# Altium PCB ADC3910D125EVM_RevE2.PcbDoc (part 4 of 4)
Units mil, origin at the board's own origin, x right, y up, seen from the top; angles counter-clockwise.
Board outline 4000 x 2716.54 mil, 6 copper layers (Top Layer, L2 GND, L3 PWR, L4 PWR, L5 GND, Bottom Layer), stack 60.99 mil thick; 318 components, 203 nets, 1298 pads, 559 vias.
Unrouted connection lines stored in the file: 5.
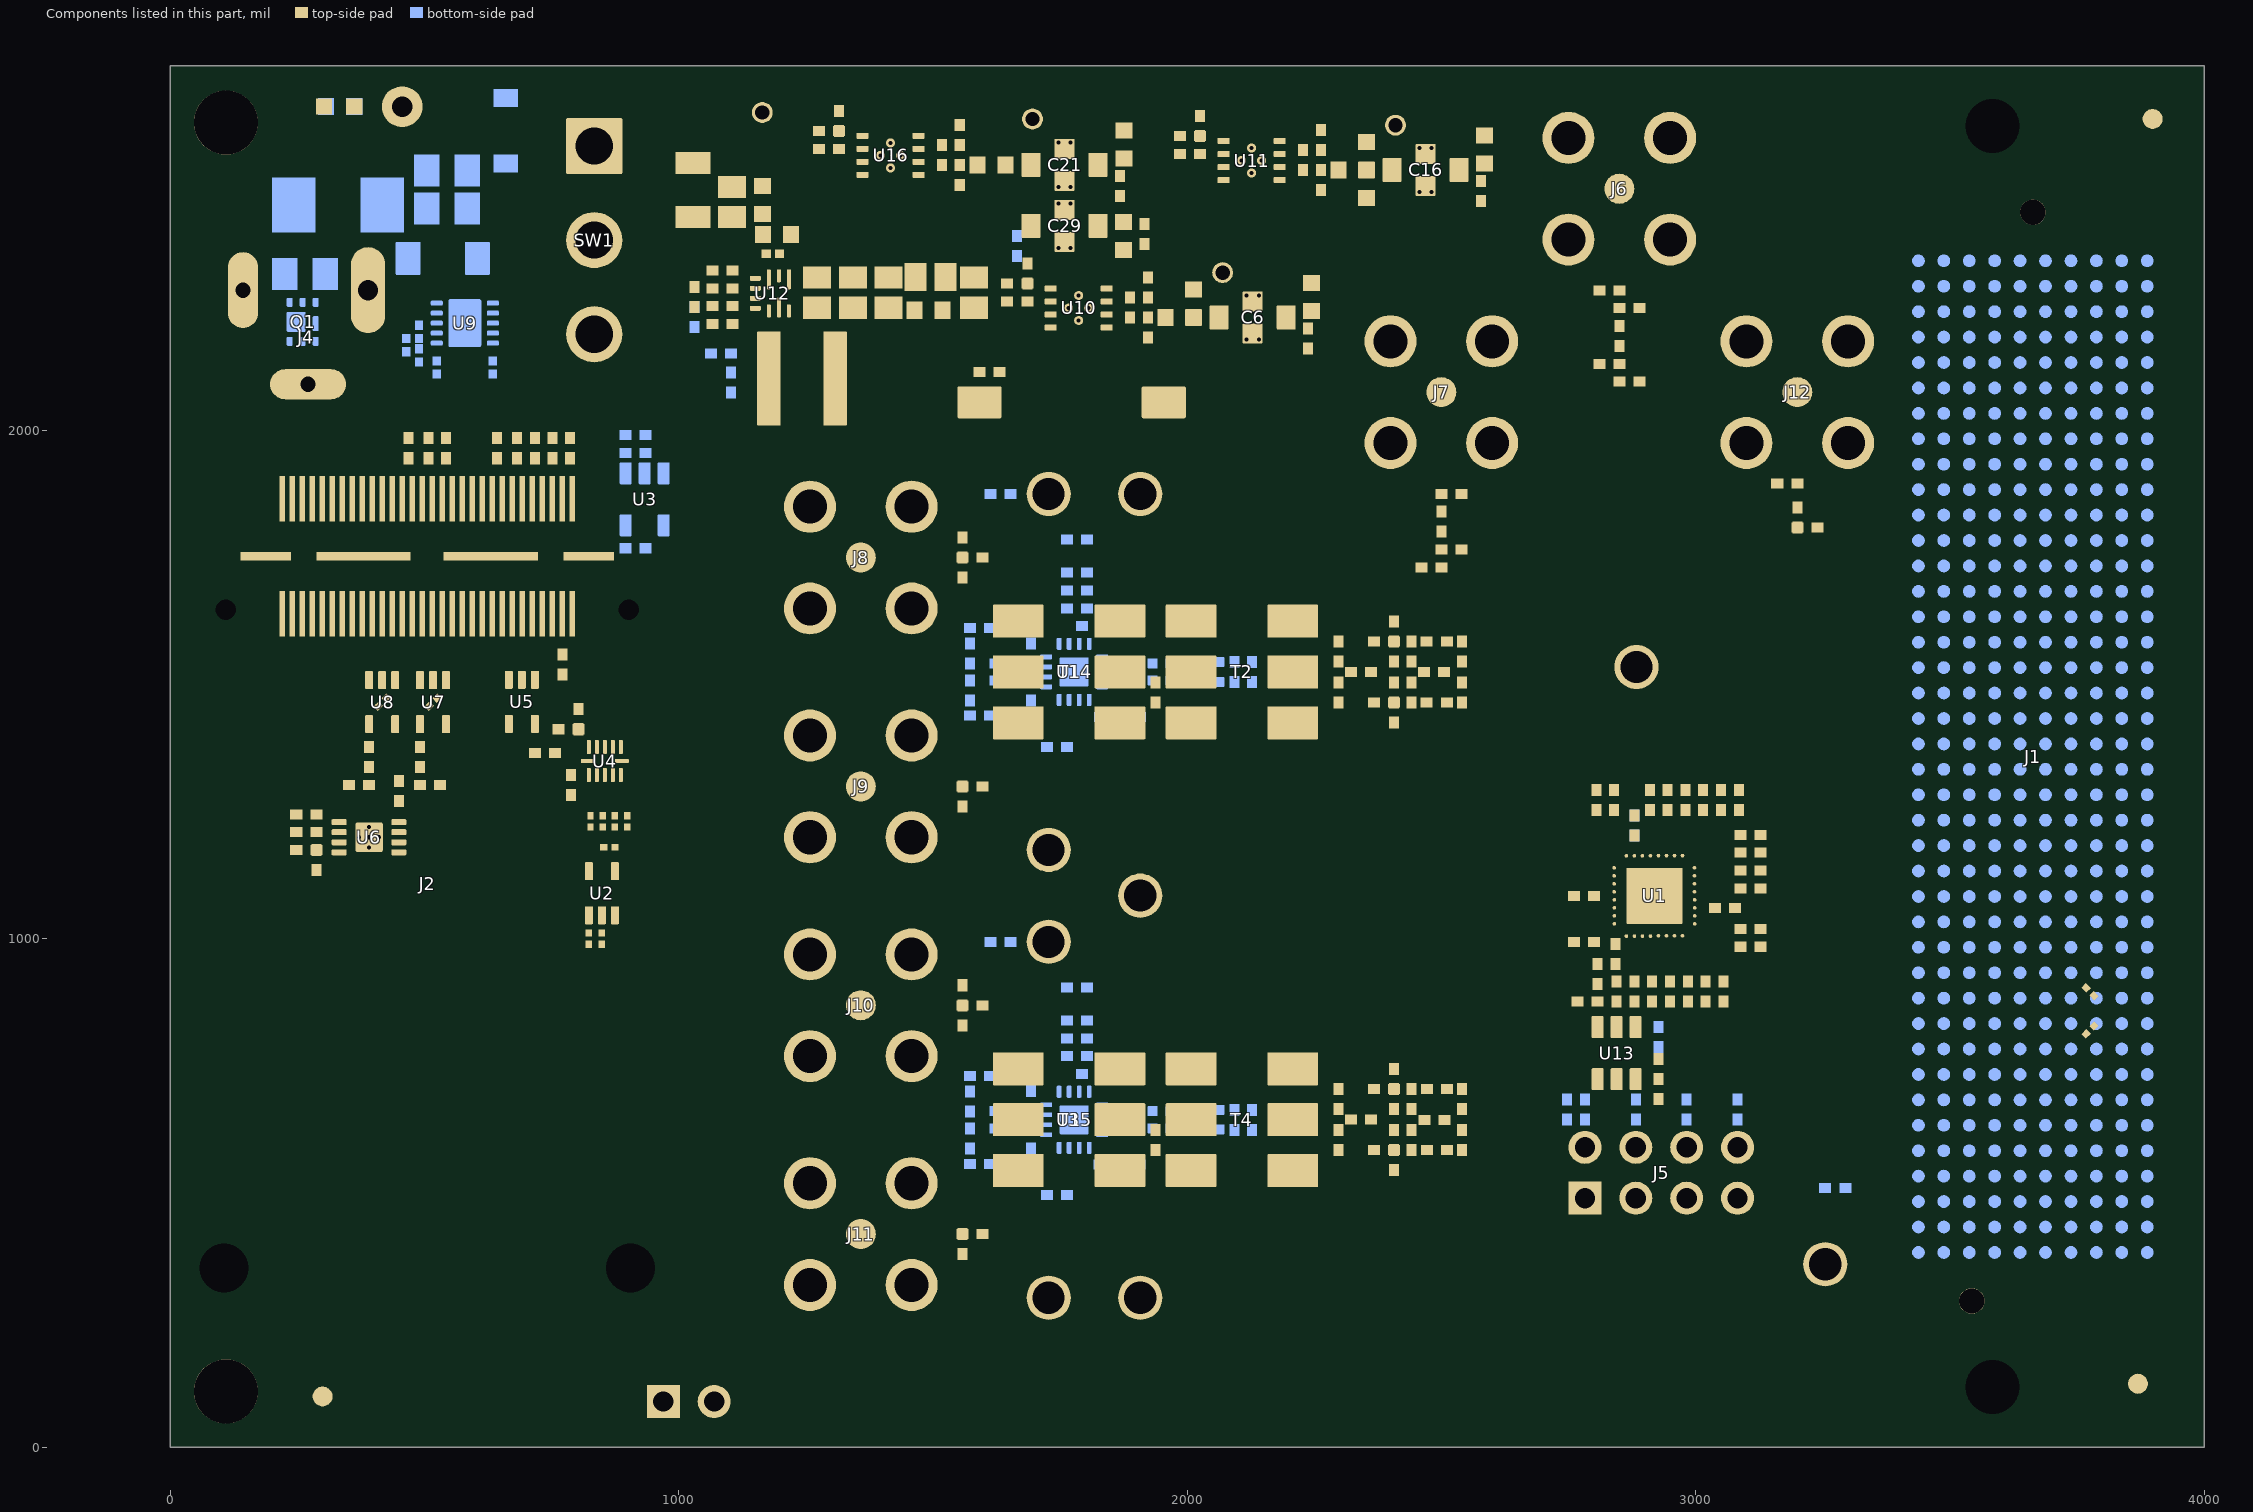
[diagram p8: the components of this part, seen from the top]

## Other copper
Top Layer:
  region net 4V_LDO: 1581.71,2180.1 1600.75,2180.1 ccw(c1600.75,2188.17) 1608.88,2188.17 1608.88,2219.31 1608.88,2262.62 1553.76,2262.62 cw(c1553.76,2269.8) 1546.57,2269.8 1546.57,2328.56 1503.27,2328.56 1503.27,2219.31 1536.16,2219.31 cw(c1536.16,2204.29) 1551.18,2204.29 1551.18,2189.28 ccw(c1560.35,2189.28) 1560.35,2180.1 1580.75,2180.1 ccw(c1580.75,2188.17)
  region net NetC21_1: 1707.09,2378.39 ccw(c1707.09,2383.11) 1711.81,2383.11 1711.81,2500.11 ccw(c1710.09,2500.11) 1711.81,2500.12 1711.81,2580.23 cw(c1716.87,2580.23) 1716.87,2585.29 ccw(c1716.87,2593.42) 1725,2593.42 1725,2629.24 ccw(c1716.87,2629.24) 1716.87,2637.37 1675.4,2637.37 ccw(c1675.4,2630.65) 1668.68,2630.65 1668.68,2593.19 ccw(c1672.41,2593.19) 1672.41,2589.47 cw(c1672.41,2587.47) 1674.41,2587.47 1674.41,2543.57 cw(c1669.58,2543.57) 1669.58,2538.74 1627.36,2538.74 ccw(c1627.36,2537.76) 1626.38,2537.76 1626.38,2506.26 ccw(c1627.36,2506.26) 1627.36,2505.28 1636.66,2505.28 cw(c1636.66,2467.57) 1674.36,2467.57 ccw(c1677.59,2467.57) 1674.41,2467.03 1674.41,2381.77 ccw(c1677.8,2381.77) 1677.8,2378.39
  region net REF_3p3V: 1806.3,2520.47 1806.31,2500.03 ccw(c1807.95,2500.03) 1807.95,2498.39 1808.34,2498.39 1808.34,2498.47 1847.86,2498.47 cw(c1847.86,2488.07) 1858.27,2488.07 1912.56,2488.07 ccw(c1912.56,2495.51) 1920,2495.51 1920,2542.98 ccw(c1912.35,2542.98) 1912.35,2550.63 1858.32,2550.63 cw(c1853.32,2550.63) 1853.32,2545.63 1808.95,2545.63 ccw(c1808.95,2542.98) 1806.3,2542.98
  region net FDA_3V3: 1806.35,2379.96 ccw(c1808.07,2379.96) 1808.07,2378.25 1842.03,2378.25 ccw(c1842.03,2379.97) 1843.76,2379.97 1843.76,2386 cw(c1851.75,2386) 1851.75,2393.99 1925.9,2393.99 1976.94,2393.99 ccw(c1976.94,2402.89) 1985.84,2402.89 1985.84,2423.81 ccw(c1976.3,2423.81) 1976.3,2433.76 1816.72,2433.76 ccw(c1816.72,2423.39) 1806.35,2423.39
  region net GND: 1858.32,2338.87 1891.79,2338.87 1891.79,2377.02 ccw(c1885.13,2377.02) 1885.13,2383.67 1864.53,2383.67 ccw(c1864.53,2377.55) 1858.32,2377.55 1858.32,2343.03
  region net NetC27_2: 1472.14,2496.02 1472.14,2496.07 cw(c1461.72,2497.6) 1460.19,2497.6 1460.19,2506.26 1460.18,2506.26 1460.18,2532.02 cw(c1461.99,2532.02) 1461.99,2533.82 1562.83,2533.82 1567.32,2533.82 ccw(c1567.32,2538.74) 1572.24,2538.74 1603.74,2538.74 1603.74,2505.28 1513.38,2505.28 ccw(c1513.38,2499.86) 1507.96,2499.86 cw(c1504.12,2499.86) 1504.12,2496.02 1481.52,2496.02
  region net 4V_LDO: 1371.79,2496.02 ccw(c1371.79,2497.79) 1373.56,2497.79 1373.56,2506.58 1373.57,2532.24 ccw(c1372.02,2532.27) 1371.96,2533.82 1360.28,2533.82 1360.28,2533.72 1318.48,2533.72 ccw(c1318.48,2524.55) 1309.3,2524.55 1309.3,2504.15 ccw(c1317.37,2504.15) 1317.37,2496.02
  region net GND: 1858.86,2605.51 1858.86,2565.22 ccw(c1865.52,2565.22) 1865.52,2558.56 1886.34,2558.56 ccw(c1886.34,2564.6) 1892.32,2564.6 1892.32,2605.51
  region net NetC16_1: 2337.36,2528.74 ccw(c2337.36,2527.76) 2336.38,2527.76 2336.38,2496.26 ccw(c2337.36,2496.26) 2337.36,2495.28 2381.72,2495.28 cw(c2381.72,2492.58) 2384.41,2492.58 2384.41,2489.83 ccw(c2385.82,2489.8) 2385.9,2488.39 2420.08,2488.39 ccw(c2420.09,2490.11) 2421.81,2490.12 2421.81,2570.23 cw(c2426.87,2570.23) 2426.87,2575.29 ccw(c2426.87,2583.42) 2435,2583.42 2435,2619.24 ccw(c2426.87,2619.24) 2426.87,2627.37 2385.4,2627.37 ccw(c2385.4,2620.65) 2378.68,2620.65 2378.68,2583.19 ccw(c2382.41,2583.19) 2382.41,2579.47 cw(c2382.41,2577.47) 2384.41,2577.47 2384.41,2533.57 cw(c2379.58,2533.57) 2379.58,2528.74 2365.62,2528.74
  region net NetC6_1: 1997.36,2238.74 ccw(c1997.36,2237.76) 1996.38,2237.76 1996.38,2206.26 ccw(c1997.36,2206.26) 1997.36,2205.28 2041.72,2205.28 cw(c2041.72,2202.58) 2044.41,2202.58 2044.41,2199.83 ccw(c2045.82,2199.8) 2045.9,2198.39 2080.08,2198.39 ccw(c2080.09,2200.11) 2081.81,2200.12 2081.81,2280.23 cw(c2086.87,2280.23) 2086.87,2285.29 ccw(c2086.87,2293.42) 2095,2293.42 2095,2329.24 ccw(c2086.87,2329.24) 2086.87,2337.37 2045.4,2337.37 ccw(c2045.4,2330.65) 2038.68,2330.65 2038.68,2293.19 ccw(c2042.41,2293.19) 2042.41,2289.47 cw(c2042.41,2287.47) 2044.41,2287.47 2044.41,2243.57 cw(c2039.58,2243.57) 2039.58,2238.74 2025.62,2238.74
  region net 4V_LDO: 2081.79,2486.02 ccw(c2081.79,2487.8) 2083.56,2487.8 2083.56,2496.58 2083.57,2522.24 ccw(c2082.02,2522.27) 2081.96,2523.82 2070.28,2523.82 2070.28,2523.72 2028.48,2523.72 ccw(c2028.48,2514.55) 2019.3,2514.55 2019.3,2494.15 ccw(c2027.37,2494.15) 2027.37,2486.02
  region net OUT2: 2182.14,2486.02 2182.14,2486.07 cw(c2171.72,2487.6) 2170.19,2487.6 2170.19,2496.26 2170.18,2496.26 2170.18,2522.02 cw(c2171.99,2522.02) 2171.99,2523.82 2272.83,2523.82 2277.32,2523.82 ccw(c2277.32,2528.74) 2282.24,2528.74 2313.74,2528.74 2313.74,2495.28 2223.38,2495.28 ccw(c2223.38,2489.86) 2217.96,2489.86 cw(c2214.12,2489.86) 2214.12,2486.02 2191.52,2486.02
  region net IOVDD: 2516.3,2510.47 2516.31,2490.03 ccw(c2517.95,2490.03) 2517.95,2488.39 2518.34,2488.39 2518.34,2488.48 2557.86,2488.48 cw(c2557.86,2478.07) 2568.27,2478.07 2622.56,2478.07 ccw(c2622.56,2485.51) 2630,2485.51 2630,2532.98 ccw(c2622.35,2532.98) 2622.35,2540.63 2568.32,2540.63 cw(c2563.32,2540.63) 2563.32,2535.63 2518.95,2535.63 ccw(c2518.95,2532.98) 2516.3,2532.98
  region net GND: 2568.27,2595.75 2568.27,2555.45 ccw(c2574.93,2555.45) 2574.93,2548.79 2595.74,2548.79 ccw(c2595.74,2554.83) 2601.73,2554.83 2601.73,2595.75
  region net GND: 1440.37,2268.92 1489.98,2268.92 ccw(c1489.98,2276.02) 1497.08,2276.02 1497.08,2281.06 ccw(c1489.42,2281.1) 1497.08,2281.1 1497.08,2321.54 ccw(c1490.14,2321.63) 1489.94,2328.56 1444.21,2328.56 cw(c1437.32,2328.56) 1437.32,2321.67 1245.1,2321.67 cw(c1245.1,2330.49) 1236.28,2330.49 1236.28,2441.61 ccw(c1181.47,2441.61) 1181.47,2496.42 1136.94,2496.42 cw(c1136.94,2500.36) 1133,2500.36 1110.13,2500.36 cw(c1110.13,2547.6) 1062.89,2547.6 993.99,2547.6 993.99,2464.35 ccw(c1010.78,2464.35) 1010.78,2447.55 1181.31,2447.55 cw(c1181.11,2439.31) 1189.34,2439.79 1189.34,2350.99 ccw(c1191.32,2377.96) 1189.64,2350.97 1189.64,2338.91 1203.98,2338.91 cw(c1203.98,2329.76) 1213.13,2329.76 1213.13,2274.06 ccw(c1218.33,2274.06) 1218.33,2268.86 1439.63,2268.86 ccw(c1439.63,2273.44)
  region net NetC34_1: 1306,2009.27 1364.45,2009.27 ccw(c1364.45,2015.16) 1370.34,2015.16 1370.34,2207.24 cw(c1382.22,2207.44) 1382.7,2219.31 1478.88,2219.31 1478.88,2252.01 cw(c1479.64,2252.01) 1479.64,2252.77 ccw(c1469.82,2252.77) 1469.82,2262.6 1245.1,2262.6 1245.1,2262.62 1217.73,2262.62 ccw(c1217.73,2257.94) 1213.05,2257.94 1213.05,2222.3 ccw(c1216.04,2222.3) 1216.04,2219.31 1257.93,2219.31 cw(c1257.93,2192.41) 1284.83,2192.41 1284.83,2011.02 ccw(c1286.58,2011.02) 1286.58,2009.27
  region net NetL1_1: 1154.52,2011.32 ccw(c1156.57,2011.32) 1156.57,2009.27 1199.34,2009.27 ccw(c1199.34,2011.17) 1201.24,2011.17 1201.24,2259.46 ccw(c1199.23,2259.46) 1199.23,2261.47 1191.4,2261.47 ccw(c1191.4,2258.09) 1188.02,2258.09 1188.02,2216.01 cw(c1175.36,2216.01) 1175.36,2203.34 1165.07,2203.34 ccw(c1165.07,2192.82) 1154.55,2192.82 1154.55,2011.69 1154.52,2011.69
  region net +12V: 993.99,2398 1133,2398 cw(c1133,2381.03) 1149.97,2381.03 1149.97,2352.29 ccw(c1163.36,2352.29) 1161.51,2339.04 cw(c1160.69,2341.57) 1160.69,2338.91 cw(c1160.69,2330.47) 1169.13,2330.47 1169.13,2280.33 ccw(c1172.25,2280.33) 1172.25,2277.22 1177.43,2277.22 1178.31,2277.23 1179.77,2277.23 ccw(c1179.77,2278.93) 1181.47,2278.93 1181.47,2441.31 993.99,2441.31
  region net NetC50_2: 2844.56,804.73 2854.65,804.73 ccw(c2854.65,806.65) 2856.57,806.65 2856.57,886.23 ccw(c2854.62,886.23) 2854.62,888.19 2834.93,888.19 ccw(c2834.93,886.22) 2832.96,886.22 2832.96,806.38 ccw(c2834.66,806.38) 2834.66,804.73 2835.01,804.73
  region net NetC47_2: 2817.16,804.73 ccw(c2817.16,806.75) 2819.18,806.75 2819.18,921.23 ccw(c2817.21,921.23) 2817.21,923.19 2797.53,923.19 ccw(c2797.53,921.22) 2795.56,921.22 2795.56,807.03 ccw(c2797.86,807.03) 2797.86,804.73 2797.89,804.73
  region net VREF: 2819.18,938.94 2819.18,945.28 cw(c2852.21,945.28) 2852.21,978.31 2856.27,978.31 ccw(c2856.27,990) 2867.96,990 2867.96,1017.96 ccw(c2864.42,1017.96) 2864.42,1021.5 2863.63,1021.5 ccw(c2863.63,1017.96) 2860.09,1017.96 cw(c2844.07,1017.96) 2844.07,1001.93 2826.05,1001.93 ccw(c2826.05,998.57) 2822.69,998.57 2822.69,991.54 cw(c2806.48,991.54) 2806.48,975.34 2799.74,975.34 ccw(c2799.74,973.13) 2797.53,973.13 2797.53,938.94
  region net GND: 288.27,1738.8 ccw(c304.06,1738.8) 304.06,1723.01 462.48,1723.01 ccw(c462.48,1733.84) 473.31,1733.84 473.31,1770.06 ccw(c462.48,1770.06) 462.48,1780.89 304.06,1780.89 ccw(c304.06,1765.1) 288.27,1765.1 288.27,1753.61
  region net GND: 538.27,1738.8 ccw(c554.06,1738.8) 554.06,1723.01 712.48,1723.01 ccw(c712.48,1733.84) 723.31,1733.84 723.31,1770.06 ccw(c712.48,1770.06) 712.48,1780.89 554.06,1780.89 ccw(c554.06,1765.1) 538.27,1765.1 538.27,1753.61
  region net GND: 776.74,1731.81 ccw(c793.31,1743.01) 793.31,1723.01 853.31,1723.01 ccw(c853.31,1743.01) 873.31,1743.01 873.31,1760 ccw(c853.31,1760) 869.24,1772.09 ccw(c852.67,1760.89) 852.67,1780.89 792.67,1780.89 ccw(c792.67,1760.89) 772.67,1760.89 772.67,1743.9 ccw(c792.67,1743.9)
  region net GND: 141.7,1731.81 ccw(c158.27,1743.01) 158.27,1723.01 218.27,1723.01 ccw(c218.27,1743.01) 238.27,1743.01 238.27,1760 ccw(c218.27,1760) 234.2,1772.09 ccw(c217.63,1760.89) 217.63,1780.89 157.63,1780.89 ccw(c157.63,1760.89) 137.63,1760.89 137.63,1743.9 ccw(c157.63,1743.9)
  region net VCM: 2869.93,1215.04 2869.93,1191.42 cw(c2869.93,1185.52) 2875.84,1185.52 2875.84,1150.23 ccw(c2878.99,1150.23) 2878.99,1147.07 2879.77,1147.07 ccw(c2879.77,1151.01) 2883.71,1151.01 2883.71,1178.57 2883.71,1185.52 cw(c2889.62,1185.52) 2889.62,1191.42 2889.62,1215.04
  region net +1.8V_FTDI: 825.73,1308.19 ccw(c825.73,1309.88) 827.42,1309.88 827.42,1334.02 ccw(c825.7,1334.02) 825.7,1335.75 780.63,1335.75 ccw(c780.63,1333.78) 778.66,1333.78 778.66,1310.16 ccw(c780.63,1310.16) 780.63,1308.19 824.83,1308.19
  region net GND: 332.16,1176.08 319.26,1176.08 ccw(c319.26,1174.67) 317.85,1174.67 317.85,1166.18 317.81,1166.18 317.81,1150.05 ccw(c321.88,1150.05) 321.88,1145.98 342.88,1145.98 ccw(c342.88,1150.29) 347.34,1150.29 347.34,1174.32 347.34,1174.33 ccw(c345.59,1174.33) 345.59,1176.08
  region net FTDI_3V3: 449.45,1223.32 449.45,1223.34 ccw(c463.05,1224.88) 464.59,1224.88 464.59,1278.12 ccw(c459.67,1278.12) 459.67,1283.04 439.99,1283.04 439.99,1238.55 cw(c436.54,1238.55) 436.54,1235.11 ccw(c436.54,1233.64) 435.07,1233.64 435.07,1224.36 ccw(c436.27,1224.36) 436.27,1223.32 438.26,1223.32
  region net GND: 1077.89,2500.36 1077.89,2455.15 ccw(c1085.54,2455.15) 1085.54,2447.49 1125.98,2447.49 ccw(c1125.98,2454.63) 1133,2454.63 1133,2500.36
  region net GND: 1553.76,2321.67 1553.76,2276.46 ccw(c1561.42,2276.46) 1561.42,2268.8 1601.86,2268.8 ccw(c1601.86,2275.94) 1608.88,2275.94 1608.88,2321.67
  region net GND: 1385.34,2321.67 1385.34,2276.46 ccw(c1392.99,2276.46) 1392.99,2268.8 1433.44,2268.8 ccw(c1433.44,2275.94) 1440.46,2275.94 1440.46,2321.67
  region net GND: 1315.22,2321.67 1315.22,2276.46 ccw(c1322.88,2276.46) 1322.88,2268.8 1363.32,2268.8 ccw(c1363.32,2275.94) 1370.34,2275.94 1370.34,2321.67
  region net GND: 1245.1,2321.67 1245.1,2276.46 ccw(c1252.76,2276.46) 1252.76,2268.8 1293.2,2268.8 ccw(c1293.2,2275.94) 1300.22,2275.94 1300.22,2321.67
  region net IOVDD: 3050.11,1070.71 3026.48,1070.71 cw(c3020.58,1070.71) 3020.58,1064.81 2985.29,1064.81 ccw(c2985.29,1061.65) 2982.14,1061.65 2982.14,1060.87 ccw(c2986.07,1060.87) 2986.07,1056.93 3013.63,1056.93 3020.58,1056.93 cw(c3020.58,1051.03) 3026.48,1051.03 3050.11,1051.03
  region net AVDD: 1997.46,2027.46 cw(c1975.67,2027.46) 1975.67,2005.66 1934.1,2005.66 cw(c1934.1,2028.91) 1910.85,2028.91 1910.85,2080.85 cw(c1934.16,2080.85) 1934.16,2104.16 1975.9,2104.16 cw(c1975.9,2082.63) 1997.46,2082.63 1997.46,2052.24
  region net 4V_LDO: 1741.79,2196.02 ccw(c1741.79,2197.8) 1743.56,2197.8 1743.56,2206.58 1743.57,2232.24 ccw(c1742.02,2232.27) 1741.96,2233.82 1730.28,2233.82 1730.28,2233.72 1688.48,2233.72 ccw(c1688.48,2224.55) 1679.3,2224.55 1679.3,2204.15 ccw(c1687.37,2204.15) 1687.37,2196.02
  region net OUT1: 1842.14,2196.02 1842.14,2196.07 cw(c1831.72,2197.6) 1830.19,2197.6 1830.19,2206.26 1830.18,2206.26 1830.18,2232.02 cw(c1831.99,2232.02) 1831.99,2233.82 1932.83,2233.82 1937.32,2233.82 ccw(c1937.32,2238.74) 1942.24,2238.74 1973.74,2238.74 1973.74,2205.28 1883.38,2205.28 ccw(c1883.38,2199.86) 1877.96,2199.86 cw(c1874.12,2199.86) 1874.12,2196.02 1851.52,2196.02
  region net GND: 2228.27,2305.75 2228.27,2265.45 ccw(c2234.93,2265.45) 2234.93,2258.79 2255.74,2258.79 ccw(c2255.74,2264.83) 2261.73,2264.83 2261.73,2305.75
  region net AVDD: 2176.3,2220.47 2176.31,2200.03 ccw(c2177.95,2200.03) 2177.95,2198.39 2178.34,2198.39 2178.34,2198.48 2217.86,2198.48 cw(c2217.86,2188.07) 2228.27,2188.07 2282.56,2188.07 ccw(c2282.56,2195.51) 2290,2195.51 2290,2242.98 ccw(c2282.35,2242.98) 2282.35,2250.63 2228.32,2250.63 cw(c2223.32,2250.63) 2223.32,2245.63 2178.95,2245.63 ccw(c2178.95,2242.98) 2176.3,2242.98
  region net AVDD: 2788.59,1074.65 2822.69,1074.65 cw(c2822.69,1072.68) 2824.66,1072.68 2852.61,1072.68 ccw(c2852.61,1076.23) 2856.15,1076.23 2856.15,1093.15 ccw(c2853,1093.15) 2853,1096.3 2824.66,1096.3 cw(c2822.69,1096.3) 2822.69,1094.34 2788.59,1094.34
  region net NetC58_2: 2334.15,1514.86 2334.15,1534.54 2311.15,1534.54 2310.78,1534.54 cw(c2310.78,1538.14) 2307.18,1538.14 2307.18,1557.14 2287.49,1557.14 2287.49,1492.26 2307.18,1492.26 2307.18,1511.51 cw(c2310.53,1511.51) 2310.53,1514.86
  region net NetC79_2: 2334.15,634.45 2334.15,654.13 2311.15,654.13 2310.78,654.13 cw(c2310.78,657.73) 2307.18,657.73 2307.18,676.73 2287.49,676.73 2287.49,611.85 2307.18,611.85 2307.18,631.1 cw(c2310.53,631.1) 2310.53,634.45
  region net GND: 1617.96,701.95 ccw(c1625.93,701.95) 1625.93,693.99 1710.93,693.99 ccw(c1710.93,701.03) 1717.96,701.03 1717.96,786.63 ccw(c1710,786.63) 1710,794.59 1625,794.59 ccw(c1625,787.55) 1617.96,787.55 1617.96,723.95
  region net GND: 2494.26,653.83 2494.26,634.14 2527.26,634.14 2527.63,634.14 cw(c2527.63,630.54) 2531.23,630.54 2531.23,611.55 2550.92,611.55 2550.92,676.43 2531.23,676.43 2531.23,657.18 cw(c2527.88,657.18) 2527.88,653.83
  region net VCM: 2478.51,634.27 2478.51,653.95 2455.52,653.95 2455.15,653.95 cw(c2455.15,657.55) 2451.55,657.55 2451.55,676.55 2431.86,676.55 2431.86,611.67 2451.55,611.67 2451.55,630.92 cw(c2454.89,630.92) 2454.89,634.27
  region net GND: 1617.96,1582.36 ccw(c1625.93,1582.36) 1625.93,1574.4 1710.93,1574.4 ccw(c1710.93,1581.44) 1717.96,1581.44 1717.96,1667.04 ccw(c1710,1667.04) 1710,1675 1625,1675 ccw(c1625,1667.96) 1617.96,1667.96 1617.96,1604.36
  region net GND: 2493.89,1534.54 2493.89,1514.86 2526.89,1514.86 2527.26,1514.86 cw(c2527.26,1511.26) 2530.86,1511.26 2530.86,1492.26 2550.55,1492.26 2550.55,1557.14 2530.86,1557.14 2530.86,1537.89 cw(c2527.51,1537.89) 2527.51,1534.54
  region net VCM: 2478.14,1514.86 2478.14,1534.54 2455.15,1534.54 2454.78,1534.54 cw(c2454.78,1538.14) 2451.18,1538.14 2451.18,1557.14 2431.49,1557.14 2431.49,1492.26 2451.18,1492.26 2451.18,1511.51 cw(c2454.52,1511.51) 2454.52,1514.86
  region net FTDI_3V3: 245.53,1684.09 214.86,1684.09 214.86,1460.7 245.53,1460.7
  region net NetC86_2: 1853.85,611.79 1854.2,612.14 2057.96,612.14 2057.96,676.79 1817.96,676.79 1817.96,611.79 1859.15,611.79
  region net NetC64_2: 1853.85,1492.2 1854.2,1492.55 2057.96,1492.55 2057.96,1557.2 1817.96,1557.2 1817.96,1492.2 1859.15,1492.2
  region net GND: 3013.63,1072.68 2963.63,1072.68 2963.63,1080.56 3013.63,1080.56
  text ".Layer_Name" at 577,-852.06 h60
Bottom Layer:
  region net +12V_JACK: 622.95,2208.54 ccw(c625.35,2208.54) 625.35,2206.14 672.43,2206.14 ccw(c672.43,2214.9) 681.19,2214.9 681.19,2431.15 cw(c704.83,2431.15) 704.83,2454.8 890,2454.8 ccw(c890,2474.8) 910,2474.8 910,2651.49 ccw(c895.95,2651.49) 895.95,2665.55 734.35,2665.55 ccw(c734.35,2648.68) 717.48,2648.68 717.48,2575.44 cw(c684.54,2575.44) 684.54,2542.5 559.77,2542.5 559.77,2404.5 559.61,2404.5 559.61,2398.47 ccw(c569.8,2398.47) 569.8,2388.28 cw(c569.8,2378.44) 579.64,2378.44 579.64,2307.46 ccw(c581.57,2307.46) 581.57,2305.54 cw(c581.57,2264.16) 622.95,2264.16 622.95,2250.73
  region net NetC10_1: 497.79,2197.42 cw(c506.51,2197.42) 506.51,2206.14 534.14,2206.14 ccw(c534.14,2208.33) 536.33,2208.33 536.33,2352.02 ccw(c517.86,2352.02) 517.86,2370.5 469.96,2370.5 cw(c469.96,2380.83) 459.63,2380.83 459.63,2496.66 374.63,2496.66 374.63,2388.56 cw(c346.24,2388.56) 346.24,2360.17 355.71,2226.61 355.71,2224.48 ccw(c389.26,2224.48) 389.26,2190.94 426.15,2190.94 ccw(c426.15,2194.9) 430.11,2194.9 cw(c432.64,2194.9) 432.64,2197.42
  region net NetC10_1: 282.56,2242.81 cw(c282.56,2244.76) 280.62,2244.76 280.62,2276.17 280.62,2339.17 cw(c301.61,2339.17) 301.61,2360.17 390.86,2360.17 cw(c390.86,2328.04) 422.98,2328.04 422.98,2223.24 cw(c390.67,2223.24) 390.67,2190.94 387.85,2190.94 cw(c387.85,2222.69) 356.1,2222.69 ccw(c335.97,2222.69) 335.97,2242.81 288.05,2242.81
  region net GND: 636.51,2671.44 636.51,2633.09 ccw(c650.52,2633.09) 650.52,2619.07 673.11,2619.07 ccw(c673.11,2630.5) 684.54,2630.5 684.54,2671.24
  region net GND: 479.56,2404.5 531.32,2404.5 ccw(c531.32,2416) 542.82,2416 542.82,2456 ccw(c531.32,2456) 531.32,2467.5 479.56,2467.5
  region net GND: 479.56,2479.5 531.32,2479.5 ccw(c531.32,2491) 542.82,2491 542.82,2531 ccw(c531.32,2531) 531.32,2542.5 479.56,2542.5
  region net GND: 286.79,2166.04 308.01,2166.04 ccw(c308.01,2173.46) 315.43,2173.46 315.43,2214.98 ccw(c306.2,2214.98) 306.2,2224.31 281.82,2224.31 ccw(c281.82,2223.41) 280.93,2223.41 280.93,2172.33 280.64,2172.33 280.64,2167.64 ccw(c282.21,2167.64) 282.21,2166.07
  region net NetC10_2: 264.99,2166.04 ccw(c264.99,2167.88) 266.83,2167.88 266.83,2223.94 266.84,2223.94 266.84,2258.69 ccw(c265.01,2258.69) 265.01,2260.52 cw(c265.01,2274.91) 250.62,2274.91 250.62,2353.67 cw(c285.62,2353.67) 285.62,2388.67 285.62,2496.27 200.62,2496.27 200.62,2438.09 cw(c158.27,2438.09) 158.27,2395.74 ccw(c158.27,2351.47) 113.99,2351.47 113.99,2230.62 ccw(c143.86,2230.62) 143.86,2200.75 180.53,2200.75 cw(c180.53,2181.28) 200,2181.28 ccw(c215.24,2181.28) 215.24,2166.04 235.37,2166.04
  region net NetR106_2: 1769.37,1481.55 1787.36,1481.57 1810.13,1481.57 cw(c1810.13,1479.49) 1812.22,1479.49 1812.22,1456.76 cw(c1810.21,1456.76) 1810.21,1454.75 1780.7,1454.75 ccw(c1780.7,1449.42) 1775.37,1449.42 1775.37,1254.91 1775.81,1254.91 1775.81,1143.06 cw(c1752.5,1143.06) 1752.5,1119.75 1660,1119.75 cw(c1660,1139.75) 1640,1139.75 1640,1201.23 cw(c1667.96,1201.23) 1667.96,1229.19 1726.46,1229.19 ccw(c1726.46,1254.91) 1752.18,1254.91 1752.18,1390.15 ccw(c1742.29,1390.15) 1742.33,1400.05 1742.29,1400.05 cw(c1742.29,1404.7) 1737.64,1404.7 1737.64,1478.15 1737.64,1478.16 cw(c1741.04,1478.16) 1741.04,1481.55
  region net NetR129_2: 1769.37,600.79 1787.36,600.81 1810.13,600.81 cw(c1810.13,598.72) 1812.22,598.72 1812.22,576 cw(c1810.21,576) 1810.21,573.99 1780.7,573.99 ccw(c1780.7,568.66) 1775.37,568.66 1775.37,374.15 1775.81,374.15 1775.81,262.29 cw(c1752.5,262.29) 1752.5,238.99 1660,238.99 cw(c1660,258.99) 1640,258.99 1640,320.47 cw(c1667.96,320.47) 1667.96,348.43 1726.46,348.43 ccw(c1726.46,374.15) 1752.19,374.15 1752.19,509.39 ccw(c1742.29,509.39) 1742.33,519.29 1742.29,519.29 cw(c1742.29,523.94) 1737.64,523.94 1737.64,597.39 1737.64,597.4 cw(c1741.04,597.4) 1741.04,600.79
  region net VCM: 1821.27,1624.84 2480,1624.84 cw(c2480,1619.84) 2485,1619.84 2485,1514.89 cw(c2475,1514.89) 2475,1504.89 2440.16,1504.89 cw(c2440.16,1515.04) 2430,1515.04 2430,1564.1 ccw(c2415,1564.1) 2415,1579.1 1830.41,1579.1 cw(c1830.41,1588.24) 1821.27,1588.24
  region net VCM: 1821.27,744.07 2480,744.07 cw(c2480,739.07) 2485,739.07 2485,634.11 cw(c2475,634.11) 2475,624.11 2440.16,624.11 cw(c2440.16,634.27) 2430,634.27 2430,683.33 ccw(c2415,683.33) 2415,698.33 1830.42,698.33 cw(c1830.42,707.47) 1821.27,707.47
  region net NetC91_2: 1769.37,687.43 1787.36,687.42 1810.13,687.42 ccw(c1810.13,689.5) 1812.22,689.5 1812.22,712.23 ccw(c1810.21,712.23) 1810.21,714.24 1780.7,714.24 cw(c1780.7,719.57) 1775.37,719.57 1775.37,914.08 1775.81,914.08 1775.81,1025.93 ccw(c1752.5,1025.93) 1752.5,1049.24 1660,1049.24 ccw(c1660,1029.24) 1640,1029.24 1640,967.76 ccw(c1667.96,967.76) 1667.96,939.8 1726.46,939.8 cw(c1726.46,914.08) 1752.19,914.08 1752.19,778.84 cw(c1742.29,778.84) 1742.33,768.94 1742.29,768.94 ccw(c1742.29,764.29) 1737.64,764.29 1737.64,690.84 1737.64,690.83 ccw(c1741.04,690.83) 1741.04,687.43
  region net NetC70_2: 1769.37,1568.2 1787.36,1568.18 1810.13,1568.18 ccw(c1810.13,1570.27) 1812.22,1570.27 1812.22,1592.99 ccw(c1810.21,1592.99) 1810.21,1595 1780.7,1595 cw(c1780.7,1600.33) 1775.37,1600.33 1775.37,1794.84 1775.81,1794.84 1775.81,1906.69 ccw(c1752.5,1906.69) 1752.5,1930 1660,1930 ccw(c1660,1910) 1640,1910 1640,1848.52 ccw(c1667.96,1848.52) 1667.96,1820.56 1726.46,1820.56 cw(c1726.46,1794.84) 1752.18,1794.84 1752.18,1659.6 cw(c1742.29,1659.6) 1742.33,1649.7 1742.29,1649.7 ccw(c1742.29,1645.05) 1737.64,1645.05 1737.64,1571.6 1737.64,1571.59 ccw(c1741.04,1571.59) 1741.04,1568.2
  region net VCM: 1833.75,668.92 1842.57,668.92 ccw(c1842.57,671.24) 1844.89,671.24 1844.89,744.07 1821.27,744.07 1821.27,670.88 ccw(c1823.23,670.88) 1823.23,668.92
  region net VCM: 1833.75,1549.68 1842.57,1549.68 ccw(c1842.57,1552) 1844.89,1552 1844.89,1624.84 1821.27,1624.84 1821.27,1551.64 ccw(c1823.23,1551.64) 1823.23,1549.68
  text ".Layer_Name" at 577,-852.06 h60

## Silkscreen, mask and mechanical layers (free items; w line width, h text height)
Top Overlay:
  lines w7: 2731.54,275.2 2731.54,413.96 2731.76,413.96 ; 2832.55,127.8 2832.55,266.57
  text "ADC3910D125EVM / Rev E2   DC262" at 3655,1390 h60 r90
  text "SIGNAL" at 3157.1,565.16 h50
  text "UNINSTALLED = LVLSHFT ON / INSTALLED = LVLSHFT OFF" at 1130,50 h30
  text ".Layer_Name" at 577,-852.06 h60
Bottom Overlay:
  lines w10: 2821.26,307.82 2821.26,437.82 ; 2921.26,307.82 2921.26,437.82
  text "OEN" at 2758.8,305.24 h50 r270
  text "SEN" at 2858.8,305.24 h50 r270
  text "SCLK" at 2958.8,255.25 h50 r270
  text "SDATA" at 3058.8,205.27 h50 r270
  text ".Layer_Name" at 577,-852.06 h60
Top Paste:
  text ".Layer_Name" at 577,-852.06 h60
Bottom Paste:
  text ".Layer_Name" at 577,-852.06 h60
Top Solder:
  text ".Layer_Name" at 577,-852.06 h60
  text ".Layer_Name" at 577,-852.06 h60
Bottom Solder:
  text ".Layer_Name" at 577,-852.06 h60
Drill Guide:
  text ".Layer_Name" at 577,-852.06 h60
M1 Board Outline:
  the board outline again, w10
  text ".Layer_Name" at 577,-852.06 h60
M2 Board Dimensions:
  rectangle: 0,-268.56 125,-143.56
  rectangle: 125,-393.56 500,-268.56
  lines w6: 0,-268.56 1000,-268.56 ; 125,-393.56 125,-143.56 ; 250,-393.56 250,-143.56 ; 500,-393.56 500,-143.56 ; 750,-393.56 750,-143.56 ; 0,-393.56 1000,-393.56 1000,-143.56 0,-143.56 0,-393.56
  text ".Layer_Name" at 577,-852.06 h60
M3 3D STEP Top:
  text ".Layer_Name" at 577,-852.06 h60
M4 3D STEP Bottom:
  text ".Layer_Name" at 577,-852.06 h60
M5 Assembly Top:
  lines w10: -292,-923.73 6308,-923.73 ; -292,-720.4 6310,-720.4 ; -292,-517.06 -292,-1127.06 3713,-1127.06 6310,-1127.06 6310,-517.06 -291.5,-517.06 -291.5,-1127.06 1284,-1127.06 ; 2173,-1127.06 2173,-517.06 ; 3440,-720.4 3440,-517.06 ; 4280,-720.4 4280,-517.06 ; 4902,-1133.56 4902,-930.73
  text "COMPONENTS MARKED 'DNP' SHOULD NOT BE POPULATED." at 1153.5,-312.06 h60
  text "ASSEMBLY VARIANT:" at 1153,-427.56 h60
  text ".VariantName" at 2189,-427.56 h60
  text "PCB VIEWED FROM TOP SIDE" at -228.5,-649.23 h60
  text "BOARD #:" at 2248,-649.23 h60
  text ".PRJ_Number" at 2793.5,-649.23 h60
  text "REV:" at 3638,-649.23 h60
  text ".PCB_Rev" at 3929.5,-649.23 h60
  text "SVN REV:" at 4476,-649.23 h60
  text ".VersionControl_RevNumber" at 4982,-649.23 h60
  text "TID #:" at 2248,-852.56 h60
  text ".TID" at 2793.5,-852.56 h60
  text "PLOT NAME =" at -228.5,-1057.9 h60
  text ".plot_File_Name" at 577,-1057.9 h60
  text "GENERATED    :" at 2250,-1057.9 h60
  text ".Print_Date" at 3119.5,-1057.9 h60
  text ".Print_Time" at 3848.5,-1057.9 h60
  text "TEXAS INSTRUMENTS" at 5113,-1057.9 h60
M6 Assembly Bottom:
  lines w10: -292.5,-720.9 6309.5,-720.9 ; -290.5,-924.23 6309.5,-924.23 ; 1115.5,-1134.06 1115.5,-931.23 ; 1737.5,-720.9 1737.5,-517.56 ; 2577.5,-720.9 2577.5,-517.56 ; 3844.5,-1127.56 3844.5,-517.56 ; 4733.5,-1127.56 6309,-1127.56 6309,-517.56 -292.5,-517.56 -292.5,-1127.56 2304.5,-1127.56 6309.5,-1127.56 6309.5,-517.56
  text "COMPONENTS MARKED 'DNP' SHOULD NOT BE POPULATED." at 6102,-311.56 h60
  text ".VariantName" at 5058,-427.56 h60
  text "ASSEMBLY VARIANT:" at 6097,-427.56 h60
  text ".VersionControl_RevNumber" at 1035.5,-649.73 h60
  text "SVN REV:" at 1541.5,-649.73 h60
  text ".PCB_Rev" at 2088,-649.73 h60
  text "REV:" at 2379.5,-649.73 h60
  text ".PRJ_Number" at 3224,-649.73 h60
  text "BOARD #:" at 3769.5,-649.73 h60
  text "PCB VIEWED FROM BOTTOM SIDE" at 6246,-649.73 h60
  text ".TID" at 3224,-853.06 h60
  text "TID #:" at 3769.5,-853.06 h60
  text "TEXAS INSTRUMENTS" at 904.5,-1058.4 h60
  text ".Print_Time" at 2169,-1058.4 h60
  text ".Print_Date" at 2898,-1058.4 h60
  text "GENERATED    :" at 3767.5,-1058.4 h60
  text ".plot_File_Name" at 5440.5,-1058.4 h60
  text "PLOT NAME =" at 6246,-1058.4 h60
M9 Title Sheet:
  drawing of 57 lines, arcs and shapes, not listed
  text "1" at 739.84,8042.94 h70
  text "2" at 3235.5,8042.94 h70
  text "3" at 5724.84,8042.94 h70
  text "4" at 8231.51,8042.94 h70
  text "5" at 10730.5,8042.94 h70
  text "6" at 13235.5,8042.94 h70
  text "A" at -416.5,6899.94 h70
  text "A" at 14383.5,6899.94 h70
  text "B" at -416.5,4519.94 h70
  text "B" at 14383.5,4519.94 h70
  text "C" at -416.5,2144.94 h70
  text "C" at 14383.5,2144.94 h70
  text "PROJECT TITLE:" at 11343.5,283.94 h45
  text ".PRJ_Title" at 11393.5,150.61 h70
  text "DESIGNED FOR:" at 11343.5,-17.06 h45
  text ".PRJ_Customer" at 11393.5,-157.06 h70
  text "D" at -416.5,-225.06 h70
  text "D" at 14383.5,-225.06 h70
  text "FILE NAME:" at 11343.5,-317.06 h45
  text ".PCB_File_Name_No_Path" at 11393.5,-437.06 h70
  text "Texas Instruments (TI) and/or its licensors do not warrant the accuracy or completeness of this specification" at 6374,-598.9 h45
  text "ENGINEER:" at 11343.5,-607.06 h45
  text "LAYOUT BY:" at 12848.5,-607.06 h45
  text "or any information contained therein. TI and/or its licensors do not warrant that this design will meet" at 6329.01,-711.57 h45
  text ".PRJ_Engineer" at 11393.5,-762.06 h70
  text ".PCB_Layout" at 12899,-762.06 h70
  text "the specifications, will be suitable for your application or fit for any particular purpose, or will operate in" at 6329.01,-824.23 h45
  text ".Layer_Name" at 577,-852.06 h60
  text "ALTIUM DESIGNER VERSION:" at 12848.5,-917.06 h45
  text "an implementation. TI and/or its licensors do not warrant that the design is production worthy. You should" at 6329.01,-936.9 h45
  text "completely validate and test your design implementation to confirm the system functionality for your application." at 6374,-1049.56 h45
  text ".print_Scale" at 11393.5,-1050.39 h70
  text ".Application_BuildNumber" at 12899,-1050.39 h70
  text "1" at 739.84,-1257.06 h70
  text "2" at 3235.5,-1257.06 h70
  text "3" at 5724.84,-1257.06 h70
  text "4" at 8231.51,-1257.06 h70
  text "5" at 10730.5,-1257.06 h70
  text "6" at 13235.5,-1257.06 h70
M10 Fab Notes:
  drawing of 189 lines, arcs and shapes, not listed
  text "DESIGN INFORMATION" at 12382.02,6362.61 h60
  text "MIN. TRACK WIDTH:" at 11737.46,6230.49 h60
  text "8" at 12833.7,6230.49 h60
  text "MIL" at 12988.46,6230.49 h60
  text "MIN. CLEARANCE:" at 11737.46,6106.36 h60
  text "6" at 12833.7,6106.36 h60
  text "MIL" at 12988.46,6106.36 h60
  text "MIN. VIA PAD SIZE:" at 11737.46,5982.23 h60
  text "18" at 12803.71,5982.24 h60
  text "MIL" at 12988.46,5982.23 h60
  text "0.05mm (2MIL)" at 12432.46,5852.33 h60
  text "MINIMUM ANNULAR RING" at 11408.23,5844.11 h60
  text "EXTERNAL" at 13140.46,5844.11 h60
  text "PER" at 11608.23,5733.98 h60
  text "IPC-D-275 CLASS 2 LEVEL C" at 11828.23,5733.98 h60
  text "MIL, HOLES" at 13316.46,5633.51 h60
  text "+/-" at 12924,5624.92 h60
  text "+/-" at 13778,5624.92 h60
  text "REGISTRATION TOLERANCES:" at 11408.23,5623.86 h60
  text "METAL" at 12608,5623.86 h60
  text "5" at 13184.2,5623.86 h60
  text "3" at 14017.2,5623.86 h60
  text "MIL" at 14133.46,5623.86 h60
  text "HOLE SIZE TOLERANCE (UNLESS OTHERWISE SPECIFIED):" at 11408.23,5525.54 h60
  text "+/-" at 13778,5522.67 h60
  text "3" at 14017.2,5521.61 h60
  text "MIL" at 14133.46,5521.6 h60
  text "MATERIAL:" at 11333.46,5383.96 h60
  text "FR-4 High Tg" at 12319.9,5255.43 h60
  text "X" at 12175.46,5247.44 h60
  text "FR-408" at 11754.46,5242.93 h60
  text "OTHER" at 13242.46,5242.93 h60
  text "62 MIL (1.6mm) +/-10%" at 12074.56,5099.9 h60
  text "X" at 11954.46,5097.44 h60
  text "THICKNESS:" at 11408.23,5091.67 h60
  text "OTHER" at 13359.46,5091.67 h60
  text "TOLERANCE:" at 11408.23,4953.36 h60
  text "X" at 12256.46,4953.36 h60
  text "ANSI IPC-6012 TYPE 3 CLASS 2" at 12434.48,4953.36 h60
  text "OTHER +/-" at 12434.46,4809.17 h60
  text "BOW & TWIST:" at 11408.23,4663.98 h60
  text "X" at 12256.46,4663.98 h60
  text "ANSI IPC-6012 TYPE 3 CLASS 2" at 12434.48,4663.98 h60
  text "OTHER +/-" at 12434.46,4517.29 h60
  text "DRILLING:" at 11333.46,4386.67 h60
  text "NC_DRILL FILES" at 13094.46,4281.48 h60
  text "REFERENCE:" at 11408.23,4277.54 h60
  text "X" at 12065.46,4277.44 h60
  text "AS SHOWN" at 12243.46,4277.54 h60
  text "X" at 12966.46,4277.54 h60
  text "OTHER" at 13392.46,4135.29 h60
  text "PTH COPPER THICKNESS:" at 11407.91,4131.76 h60
  text "X" at 12547.14,4131.76 h60
  text "20-30 um" at 12675.14,4131.76 h60
  text "BOARD FINISH:" at 11333.46,3984.16 h60
  text "SILKSCREEN:" at 11488.68,3874.04 h60
  text "X" at 12446.46,3874.04 h60
  text "TOP" at 12563.46,3874.04 h60
  text "X" at 12956.46,3874.04 h60
  text "BOTTOM" at 13074.46,3874.04 h60
  text "SILKSCREEN COLOR:" at 11488.68,3718.85 h60
  text "WHITE" at 12563.46,3718.85 h60
  text "OTHER" at 13074.46,3718.85 h60
  text "X" at 12450,3715 h60
  text "X" at 13165,3585 h60
  text "GREEN" at 12694.46,3575.4 h60
  text "OTHER" at 13312.46,3575.4 h60
  text "RED" at 13656.67,3575.81 h60
  text "SOLDER RESIST COLOR:" at 11488.68,3568.53 h60
  text "X" at 12576.46,3421.15 h60
  text "MATTE" at 12694.46,3421.15 h60
  text "SEMI-GLOSS" at 13312,3420.51 h60
  text "IMMERSION GOLD (ENIG)" at 12394.46,3248.38 h60
  text "ENEPIG" at 13732,3241.15 h60
  text "SURFACE FINISH:" at 11333.46,3240.15 h60
  text "X" at 12216.46,3240.15 h60
  text "IMM. TIN/SILVER OR EQUIV" at 11663,3102.84 h60
  text "OTHER" at 13094.46,3098.9 h60
  text "ARRAY/PANEL:" at 11333.46,2943.52 h60
  text "CUT AND TRIM PER M1 BOARD OUTLINE" at 12394.46,2935.3 h60
  text "N.C. ROUTE" at 12394.46,2799.34 h60
  text "X" at 13082.46,2799.34 h60
  text "V. SCORE" at 13260.46,2799.34 h60
  text "CERTIFICATION:" at 11333.46,2670.21 h60
  text "MATERIALS AND WORKMANSHIP FOR ALL PCBS" at 12058.46,2670.21 h60
  text "TO MEET OR EXCEED THE REQUIREMENTS OF:" at 12058.46,2576.15 h60
  text "X" at 11695.97,2447.52 h60
  text "ANSI IPC-A-600F CLASS ->" at 11823.96,2447.52 h60
  text "X" at 13471.97,2447.52 h60
  text "2" at 13581.96,2447.52 h60
  text "1" at 13266.96,2446.02 h60
  text "3" at 13935.96,2446.02 h60
  text "X" at 12507.97,2299.83 h60
  text "RoHS" at 12635.96,2299.83 h60
  text "OTHER" at 13280.36,2299.83 h60
  text "PER ORDER" at 13677.42,2299.83 h60
  text "ALL BOARDS MUST MEET OR EXCEED UL94-V0 REQUIREMENTS." at 11361,2146 h60
  text "PCB MUST BEAR THE UL94V-0 UL REGISTERED MATERIAL ID NUMBER" at 11361,2029.94 h60
  text "ADDITIONAL REQUIREMENTS:" at 11333.46,1860.52 h60
  text "MICROSECTION:" at 11408.23,1753.39 h60
  text "YES" at 12313.96,1753.39 h60
  text "REQUIRED" at 13175.46,1609.06 h60
  text "BARE BOARD ELEC. TEST:" at 11408.23,1606.2 h60
  text "NONE" at 12713.96,1606.2 h60
  text "X" at 13057.46,1606.2 h60
  text "PER ORDER" at 13767.46,1606.2 h60
  text "X" at 11465,1460 h60
  text "8 MIL VIAS REQUIRE NON-CONDUCTIVE FILL AND PLANARIZE" at 11576.38,1401.25 h59
  text "XX MIL VIAS REQUIRE CONDUCTIVE FILL AND PLANARIZE" at 11584.38,1297.28 h60
  text "X" at 11465,1140 h60
  text "OUTER 9.5 MIL TRACES REQUIRE 50 OHM SINGLE-ENDED IMPEDANCE" at 11583.39,1133.89 h58
  text "LAYER 2 & 3 (INNER LAYERS) XX MIL WIDE, XX MIL SPACE / TRACES REQUIRE 100 OHM DIFFERENTIAL IMPEDANCE" at 11575.39,898.18 h60
  text ".Layer_Name" at 577,-852.06 h60
M11 Gerber Information:
  lines w10: -292,-923.73 6308,-923.73 ; -292,-720.4 6310,-720.4 ; -292,-517.06 -292,-1127.06 3713,-1127.06 6310,-1127.06 6310,-517.06 -291.5,-517.06 -291.5,-1127.06 1284,-1127.06 ; 2173,-1127.06 2173,-517.06 ; 3440,-720.4 3440,-517.06 ; 4280,-720.4 4280,-517.06 ; 4902,-1133.56 4902,-930.73
  text "ALL ARTWORK VIEWED FROM TOP SIDE" at -228.5,-649.23 h60
  text "BOARD #:" at 2248,-649.23 h60
  text ".PRJ_Number" at 2793.5,-649.23 h60
  text "REV:" at 3638,-649.23 h60
  text ".PCB_Rev" at 3929.5,-649.23 h60
  text "SVN REV:" at 4476,-649.23 h60
  text ".VersionControl_RevNumber" at 4982,-649.23 h60
  text "LAYER NAME =" at -228.5,-852.06 h60
  text "TID #:" at 2248,-852.56 h60
  text ".TID" at 2793.5,-852.56 h60
  text "PLOT NAME =" at -228.5,-1057.9 h60
  text ".plot_File_Name" at 577,-1057.9 h60
  text "GENERATED    :" at 2250,-1057.9 h60
  text ".Print_Date" at 3119.5,-1057.9 h60
  text ".Print_Time" at 3848.5,-1057.9 h60
  text "TEXAS INSTRUMENTS" at 5113,-1057.9 h60
M12 Stackup:
  drawing of 399 lines, arcs and shapes, not listed
  text "Layer" at 4895.58,2115 h60
  text "Name" at 5305.49,2115 h60
  text "Material" at 6235.23,2115 h60
  text "Thickness" at 7095,2115 h60
  text "Constant" at 7744.84,2115 h60
  text "Board Layer Stack" at 8314.7,2115 h60
  text "Top Overlay" at 5305.49,1995 h60
  text "Top Solder" at 5305.49,1875 h60
  text "Solder Resist" at 6235.23,1875 h60
  text "0.50mil" at 7095,1875 h60
  text "3.5" at 7744.84,1875 h60
  text "1" at 4895.58,1755 h60
  text "Top Layer" at 5305.49,1755 h60
  text "1.40mil" at 7095,1755 h60
  text "Dielectric1" at 5305.49,1635 h60
  text "FR4-370HR" at 6235.23,1635 h60
  text "5.00mil" at 7095,1635 h60
  text "3.88" at 7744.84,1635 h60
  text "2" at 4895.58,1515 h60
  text "L2 GND" at 5305.49,1515 h60
  text "1.42mil" at 7095,1515 h60
  text "Dielectric 3" at 5305.49,1395 h60
  text "PP-006" at 6235.23,1395 h60
  text "2.80mil" at 7095,1395 h60
  text "4.1" at 7744.84,1395 h60
  text "3" at 4895.58,1275 h60
  text "L3 PWR" at 5305.49,1275 h60
  text "CF-004" at 6235.23,1275 h60
  text "1.38mil" at 7095,1275 h60
  text "Dielectric 2" at 5305.49,1155 h60
  text "FR4-370HR" at 6235.23,1155 h60
  text "37.00mil" at 7095,1155 h60
  text "4.05" at 7744.84,1155 h60
  text "4" at 4895.58,1035 h60
  text "L4 PWR" at 5305.49,1035 h60
  text "CF-004" at 6235.23,1035 h60
  text "1.38mil" at 7095,1035 h60
  text "Dielectric 4" at 5305.49,915 h60
  text "PP-006" at 6235.23,915 h60
  text "2.80mil" at 7095,915 h60
  text "4.1" at 7744.84,915 h60
  text "5" at 4895.58,795 h60
  text "L5 GND" at 5305.49,795 h60
  text "1.42mil" at 7095,795 h60
  text "Dielectric 1" at 5305.49,675 h60
  text "FR4-370HR" at 6235.23,675 h60
  text "5.00mil" at 7095,675 h60
  text "3.88" at 7744.84,675 h60
  text "6" at 4895.58,555 h60
  text "Bottom Layer" at 5305.49,555 h60
  text "1.40mil" at 7095,555 h60
  text "Bottom Solder" at 5305.49,435 h60
  text "Solder Resist" at 6235.23,435 h60
  text "0.50mil" at 7095,435 h60
  text "3.5" at 7744.84,435 h60
  text "Bottom Overlay" at 5305.49,315 h60
  text "Total board thickness:" at 4895.58,195 h60
  text "61.99mil" at 7095,195 h60
  text ".Layer_Name" at 577,-852.06 h60
M13 Component Bodies Top:
  text ".Layer_Name" at 577,-852.06 h60
M14 Component Bodies Bottom:
  text ".Layer_Name" at 577,-852.06 h60
M15 Courtyards Top:
  text ".Layer_Name" at 577,-852.06 h60
M16 Courtyards Bottom:
  text ".Layer_Name" at 577,-852.06 h60
Drill Drawing:
  drawing of 182 lines, arcs and shapes, not listed
  text "Symbol" at 5172.76,4695.13 h72
  text "Quantity" at 5472.91,4695.13 h72
  text "Finished Hole Size" at 5804.6,4695.13 h72
  text "Plated" at 6440.46,4695.13 h72
  text "Hole Type" at 6699.26,4695.13 h72
  text "Drill Layer Pair" at 7074.01,4695.13 h72
  text "Hole Tolerance" at 7796.55,4695.13 h72
  text "2" at 5472.91,4571.1 h60
  text "40.16mil (1.020mm)" at 5804.6,4571.1 h60
  text "NPTH" at 6440.46,4571.1 h60
  text "Round" at 6699.26,4571.1 h60
  text "Top Layer - Bottom Layer" at 7074.01,4571.1 h60
  text "2" at 5472.91,4447.07 h60
  text "50.00mil (1.270mm)" at 5804.6,4447.07 h60
  text "NPTH" at 6440.46,4447.07 h60
  text "Round" at 6699.26,4447.07 h60
  text "Top Layer - Bottom Layer" at 7074.01,4447.07 h60
  text "2" at 5472.91,4323.05 h60
  text "96.46mil (2.450mm)" at 5804.6,4323.05 h60
  text "NPTH" at 6440.46,4323.05 h60
  text "Round" at 6699.26,4323.05 h60
  text "Top Layer - Bottom Layer" at 7074.01,4323.05 h60
  text "2" at 5472.91,4199.02 h60
  text "105.91mil (2.690mm)" at 5804.6,4199.02 h60
  text "NPTH" at 6440.46,4199.02 h60
  text "Round" at 6699.26,4199.02 h60
  text "Top Layer - Bottom Layer" at 7074.01,4199.02 h60
  text "2" at 5472.91,4074.99 h60
  text "125.98mil (3.200mm)" at 5804.6,4074.99 h60
  text "NPTH" at 6440.46,4074.99 h60
  text "Round" at 6699.26,4074.99 h60
  text "Top Layer - Bottom Layer" at 7074.01,4074.99 h60
  text "37" at 5472.91,3950.97 h60
  text "7.87mil (0.200mm)" at 5804.6,3950.97 h60
  text "PTH" at 6440.46,3950.97 h60
  text "Round" at 6699.26,3950.97 h60
  text "Top Layer - Bottom Layer" at 7074.01,3950.97 h60
  text "546" at 5472.91,3826.94 h60
  text "8.00mil (0.203mm)" at 5804.6,3826.94 h60
  text "PTH" at 6440.46,3826.94 h60
  text "Round" at 6699.26,3826.94 h60
  text "Top Layer - Bottom Layer" at 7074.01,3826.94 h60
  text "9" at 5472.91,3702.91 h60
  text "11.81mil (0.300mm)" at 5804.6,3702.91 h60
  text "PTH" at 6440.46,3702.91 h60
  text "Round" at 6699.26,3702.91 h60
  text "Top Layer - Bottom Layer" at 7074.01,3702.91 h60
  text "4" at 5472.91,3578.89 h60
  text "28.00mil (0.711mm)" at 5804.6,3578.89 h60
  text "PTH" at 6440.46,3578.89 h60
  text "Round" at 6699.26,3578.89 h60
  text "Top Layer - Bottom Layer" at 7074.01,3578.89 h60
  text "11" at 5472.91,3454.86 h60
  text "40.00mil (1.016mm)" at 5804.6,3454.86 h60
  text "PTH" at 6440.46,3454.86 h60
  text "Round" at 6699.26,3454.86 h60
  text "Top Layer - Bottom Layer" at 7074.01,3454.86 h60
  text "9" at 5472.91,3330.83 h60
  text "63.00mil (1.600mm)" at 5804.6,3330.83 h60
  text "PTH" at 6440.46,3330.83 h60
  text "Round" at 6699.26,3330.83 h60
  text "Top Layer - Bottom Layer" at 7074.01,3330.83 h60
  text "28" at 5472.91,3206.8 h60
  text "66.93mil (1.700mm)" at 5804.6,3206.8 h60
  text "PTH" at 6440.46,3206.8 h60
  text "Round" at 6699.26,3206.8 h60
  text "Top Layer - Bottom Layer" at 7074.01,3206.8 h60
  text "3" at 5472.91,3082.78 h60
  text "72.84mil (1.850mm)" at 5804.6,3082.78 h60
  text "PTH" at 6440.46,3082.78 h60
  text "Round" at 6699.26,3082.78 h60
  text "Top Layer - Bottom Layer" at 7074.01,3082.78 h60
  text "A" at 5147.51,3072.79 h55.12
  text "2" at 5472.91,2958.75 h60
  text "29.92mil (0.760mm)" at 5804.6,2958.75 h60
  text "PTH" at 6440.46,2958.75 h60
  text "Slot" at 6699.26,2958.75 h60
  text "Top Layer - Bottom Layer" at 7074.01,2958.75 h60
  text "1" at 5472.91,2834.72 h60
  text "39.76mil (1.010mm)" at 5804.6,2834.72 h60
  text "PTH" at 6440.46,2834.72 h60
  text "Slot" at 6699.26,2834.72 h60
  text "Top Layer - Bottom Layer" at 7074.01,2834.72 h60
  text "660 Total" at 5472.91,2710.7 h60
  text "Slot definitions :" at 5172.76,2623.88 h60
  text "Routed Path Length" at 5622.2,2623.88 h60
  text "= Calculated from tool start centre position to tool end centre position." at 6160.55,2623.88 h60
  text "Hole Length" at 5622.2,2574.27 h60
  text "= Routed Path Length + Tool Size = Slot length as defined in the PCB layout" at 5961.25,2574.27 h60
  text ".Layer_Name" at 577,-852.06 h60
M17 Embedded Cavity:
  text ".Layer_Name" at 577,-852.06 h60
M18 Embedded Assembly:
  text ".Layer_Name" at 577,-852.06 h60
M19 Embedded Keepout:
  text ".Layer_Name" at 577,-852.06 h60

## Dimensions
0,-393.56 to 1000,-393.56 on M2 Board Dimensions
0,0 to 0,2716.54 on M2 Board Dimensions
0,0 to 4000,0 on M2 Board Dimensions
